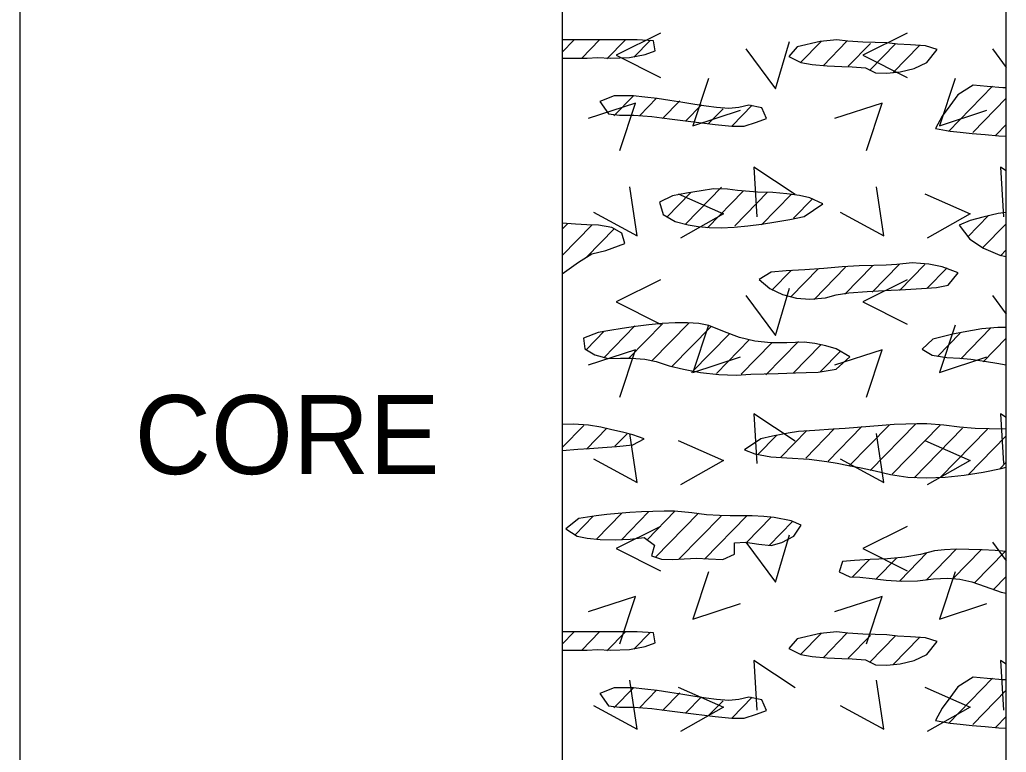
# Model space of a CAD drawing. Extents: x -0.01 to 0.83, y -0.63 to 1.27.
# Drawn here: x 0.75 to 0.8333, y -0.3617 to -0.2998 of the extents above; entities that cross this region are included whole.
import ezdxf

# ---------------------------------------------------------------- set-up
doc = ezdxf.new("R2010")
doc.units = 0

msp = doc.modelspace()

# ---------------------------------------------------------------- linework, layer by layer
for points in [[(0.749999, 1.220831), (0.749999, -0.621832)], [(0.749999, 1.220831), (0.749999, -0.621832)], [(0.795832, 1.220831), (0.795832, -0.621832)], [(0.833332, -0.621832), (0.833332, 1.138431)], [(0.795832, -0.302518), (0.796808, -0.301518)], [(0.798985, -0.3015), (0.797473, -0.303049)], [(0.801161, -0.301483), (0.799593, -0.30309)], [(0.804125, -0.300918), (0.800375, -0.302793), (0.804125, -0.304668)], [(0.803281, -0.301523), (0.801883, -0.302955)], [(0.811342, -0.302259), (0.813842, -0.305634), (0.815029, -0.301634)], [(0.817701, -0.301624), (0.815961, -0.303407)], [(0.819878, -0.301607), (0.817852, -0.303683)], [(0.824958, -0.300918), (0.821208, -0.302793), (0.824958, -0.304668)], [(0.821854, -0.301795), (0.819972, -0.303724)], [(0.824002, -0.301807), (0.821778, -0.304086)], [(0.826007, -0.301964), (0.823783, -0.304244)], [(0.832175, -0.302259), (0.833332, -0.30382)], [(0.808181, -0.30475), (0.806868, -0.30875), (0.810868, -0.307437)], [(0.829014, -0.30475), (0.827702, -0.30875), (0.831702, -0.307437)], [(0.832167, -0.30541), (0.828441, -0.309228)], [(0.801877, -0.306184), (0.800195, -0.307907)], [(0.803798, -0.306428), (0.80237, -0.307891)], [(0.805745, -0.306645), (0.804291, -0.308135)], [(0.833332, -0.306429), (0.830521, -0.309309)], [(0.800689, -0.31083), (0.802002, -0.30683), (0.798002, -0.308142)], [(0.80758, -0.306978), (0.806268, -0.308323)], [(0.809414, -0.307311), (0.808159, -0.308597)], [(0.811876, -0.307001), (0.810165, -0.308755)], [(0.821523, -0.31083), (0.822835, -0.30683), (0.818835, -0.308142)], [(0.833332, -0.308642), (0.832451, -0.309545)], [(0.815512, -0.314556), (0.812012, -0.312243), (0.812262, -0.316431)], [(0.833332, -0.312565), (0.832845, -0.312243), (0.833095, -0.316431)], [(0.798466, -0.316038), (0.802154, -0.318038), (0.801529, -0.313913)], [(0.806256, -0.317028), (0.809278, -0.313931)], [(0.8193, -0.316038), (0.822987, -0.318038), (0.822362, -0.313913)], [(0.804649, -0.316461), (0.806674, -0.314386)], [(0.805617, -0.314493), (0.809456, -0.316177), (0.805806, -0.318238)], [(0.80809, -0.317361), (0.811113, -0.314264)], [(0.810409, -0.317197), (0.813175, -0.314363)], [(0.812643, -0.317121), (0.815181, -0.314521)], [(0.815361, -0.316549), (0.816987, -0.314883)], [(0.82645, -0.314493), (0.83029, -0.316177), (0.826639, -0.318238)], [(0.830098, -0.318123), (0.831838, -0.31634)], [(0.796303, -0.317007), (0.795832, -0.317491)], [(0.798338, -0.317135), (0.795832, -0.319703)], [(0.797862, -0.319835), (0.800229, -0.31741)], [(0.831305, -0.319098), (0.833332, -0.317022)], [(0.832854, -0.319724), (0.833332, -0.319235)], [(0.815145, -0.323201), (0.817482, -0.320806)], [(0.817092, -0.323419), (0.819744, -0.320702)], [(0.819696, -0.322963), (0.822034, -0.320566)], [(0.822015, -0.3228), (0.824297, -0.320462)], [(0.824306, -0.322665), (0.826445, -0.320473)], [(0.826625, -0.322501), (0.828336, -0.320748)], [(0.815192, -0.32094), (0.813538, -0.322635)], [(0.804125, -0.321751), (0.800375, -0.323626), (0.804125, -0.325501)], [(0.811342, -0.323092), (0.813842, -0.326467), (0.815029, -0.322467)], [(0.824958, -0.321751), (0.821208, -0.323626), (0.824958, -0.325501)], [(0.832175, -0.323092), (0.833332, -0.324654)], [(0.799328, -0.328345), (0.801951, -0.325657)], [(0.801419, -0.328416), (0.804299, -0.325464)], [(0.806532, -0.325388), (0.803395, -0.328603)], [(0.805059, -0.329111), (0.808397, -0.325691)], [(0.808181, -0.325583), (0.806868, -0.329583), (0.810868, -0.32827)], [(0.829014, -0.325583), (0.827702, -0.329583), (0.831702, -0.32827)], [(0.832025, -0.325824), (0.829489, -0.328424)], [(0.799375, -0.326083), (0.797863, -0.327633)], [(0.809973, -0.326288), (0.806747, -0.329594)], [(0.827512, -0.328236), (0.82945, -0.326251)], [(0.811636, -0.326796), (0.808841, -0.32966)], [(0.813527, -0.327072), (0.810936, -0.329726)], [(0.813032, -0.329792), (0.815789, -0.326966)], [(0.815342, -0.329637), (0.817681, -0.327241)], [(0.831379, -0.328699), (0.833332, -0.326698)], [(0.800689, -0.331663), (0.802002, -0.327663), (0.798002, -0.328976)], [(0.817605, -0.329532), (0.819344, -0.327749)], [(0.821523, -0.331663), (0.822835, -0.327663), (0.818835, -0.328976)], [(0.833327, -0.328915), (0.833332, -0.32891)], [(0.815512, -0.335389), (0.812012, -0.333077), (0.812262, -0.337264)], [(0.833332, -0.333398), (0.832845, -0.333077), (0.833095, -0.337264)], [(0.797655, -0.334062), (0.795832, -0.335931)], [(0.818285, -0.337083), (0.821137, -0.334161)], [(0.820035, -0.337503), (0.823455, -0.333998)], [(0.825691, -0.333921), (0.82184, -0.337866)], [(0.827752, -0.334021), (0.823702, -0.33817)], [(0.799604, -0.334278), (0.797864, -0.336061)], [(0.798466, -0.336872), (0.802154, -0.338872), (0.801529, -0.334747)], [(0.801295, -0.334757), (0.800268, -0.335809)], [(0.813923, -0.334915), (0.812354, -0.336522)], [(0.814303, -0.336738), (0.816499, -0.334489)], [(0.816395, -0.336808), (0.818789, -0.334353)], [(0.8193, -0.336872), (0.822987, -0.338872), (0.822362, -0.334747)], [(0.829644, -0.334296), (0.825565, -0.338474)], [(0.831735, -0.334365), (0.827743, -0.338455)], [(0.833332, -0.334942), (0.830118, -0.338235)], [(0.805617, -0.335327), (0.809456, -0.33701), (0.805806, -0.339072)], [(0.82645, -0.335327), (0.83029, -0.33701), (0.826639, -0.339072)], [(0.832808, -0.337691), (0.833332, -0.337155)], [(0.79871, -0.343662), (0.800849, -0.341471)], [(0.800827, -0.343706), (0.803111, -0.341366)], [(0.805344, -0.341291), (0.802987, -0.343706)], [(0.80367, -0.345218), (0.807321, -0.341477)], [(0.798444, -0.341722), (0.796912, -0.343292)], [(0.805714, -0.345336), (0.809241, -0.341722)], [(0.811418, -0.341705), (0.807854, -0.345358)], [(0.811407, -0.343929), (0.81348, -0.341804)], [(0.815282, -0.34217), (0.813313, -0.344188)], [(0.804125, -0.342584), (0.800375, -0.344459), (0.804125, -0.346334)], [(0.811342, -0.343925), (0.813842, -0.3473), (0.815029, -0.3433)], [(0.824958, -0.342584), (0.821208, -0.344459), (0.824958, -0.346334)], [(0.832175, -0.343925), (0.833332, -0.345487)], [(0.824327, -0.347193), (0.82666, -0.344803)], [(0.829094, -0.34452), (0.826565, -0.347113)], [(0.828848, -0.346985), (0.831218, -0.344557)], [(0.833245, -0.344692), (0.830651, -0.347351)], [(0.820346, -0.346847), (0.821763, -0.345395)], [(0.822335, -0.347022), (0.824076, -0.345237)], [(0.808181, -0.346416), (0.806868, -0.350416), (0.810868, -0.349104)], [(0.829014, -0.346416), (0.827702, -0.350416), (0.831702, -0.349104)], [(0.833332, -0.346817), (0.832267, -0.347909)], [(0.800689, -0.352497), (0.802002, -0.348497), (0.798002, -0.349809)], [(0.821523, -0.352497), (0.822835, -0.348497), (0.818835, -0.349809)], [(0.795832, -0.352518), (0.796808, -0.351518)], [(0.798985, -0.3515), (0.797473, -0.353049)], [(0.801161, -0.351483), (0.799593, -0.35309)], [(0.803281, -0.351523), (0.801883, -0.352955)], [(0.817701, -0.351624), (0.815961, -0.353407)], [(0.819878, -0.351607), (0.817852, -0.353683)], [(0.821854, -0.351795), (0.819972, -0.353724)], [(0.824002, -0.351806), (0.821778, -0.354086)], [(0.826007, -0.351964), (0.823783, -0.354244)], [(0.815512, -0.356223), (0.812012, -0.35391), (0.812262, -0.358098)], [(0.833332, -0.354232), (0.832845, -0.35391), (0.833095, -0.358098)], [(0.798466, -0.357705), (0.802154, -0.359705), (0.801529, -0.35558)], [(0.8193, -0.357705), (0.822987, -0.359705), (0.822362, -0.35558)], [(0.832167, -0.35541), (0.828441, -0.359227)], [(0.801877, -0.356184), (0.800195, -0.357907)], [(0.803798, -0.356428), (0.80237, -0.35789)], [(0.805745, -0.356645), (0.804291, -0.358135)], [(0.805617, -0.35616), (0.809456, -0.357843), (0.805806, -0.359905)], [(0.82645, -0.35616), (0.83029, -0.357843), (0.826639, -0.359905)], [(0.833332, -0.356429), (0.830521, -0.359309)], [(0.80758, -0.356978), (0.806268, -0.358323)], [(0.809414, -0.357311), (0.808159, -0.358597)], [(0.811876, -0.357001), (0.810165, -0.358755)], [(0.833332, -0.358642), (0.832451, -0.359544)]]:
    msp.add_lwpolyline(points)
for points in [[(0.795832, -0.303037), (0.796757, -0.303047), (0.797925, -0.303028), (0.798816, -0.302989), (0.799915, -0.303032), (0.801515, -0.302988), (0.802823, -0.302732), (0.803666, -0.302412), (0.80354, -0.301573), (0.802165, -0.301488), (0.795832, -0.301488)], [(0.818216, -0.303682), (0.819444, -0.303741), (0.820325, -0.303781), (0.821453, -0.303849), (0.822286, -0.304263), (0.82324, -0.304307), (0.824378, -0.304202), (0.825554, -0.303914), (0.826624, -0.303409), (0.82749, -0.302312), (0.826513, -0.302009), (0.825239, -0.301908), (0.82413, -0.301844), (0.823236, -0.301738), (0.822257, -0.301719), (0.821211, -0.301695), (0.819948, -0.301604), (0.819024, -0.301488), (0.817611, -0.301627), (0.815663, -0.302071), (0.814958, -0.30291), (0.815983, -0.303398), (0.816947, -0.303574)], [(0.833053, -0.305536), (0.831709, -0.305424), (0.830539, -0.305323), (0.829246, -0.306143), (0.828567, -0.307057), (0.827924, -0.307944), (0.827345, -0.308971), (0.828579, -0.309196), (0.829451, -0.309297), (0.830451, -0.309394), (0.831549, -0.309489), (0.832716, -0.309586), (0.833332, -0.309637), (0.833332, -0.305545)], [(0.800664, -0.307839), (0.801881, -0.307846), (0.803392, -0.307974), (0.804229, -0.30807), (0.805103, -0.30818), (0.806004, -0.308298), (0.806919, -0.308419), (0.807838, -0.308537), (0.808747, -0.308647), (0.810142, -0.308789), (0.811186, -0.308777), (0.812223, -0.308432), (0.81308, -0.308147), (0.812673, -0.307245), (0.811597, -0.306998), (0.810749, -0.307196), (0.809892, -0.307279), (0.808847, -0.307198), (0.807995, -0.307087), (0.807033, -0.306943), (0.805997, -0.30678), (0.804922, -0.306612), (0.803843, -0.306455), (0.802797, -0.306323), (0.801817, -0.306231), (0.800202, -0.306222), (0.799007, -0.306695), (0.79974, -0.307738)], [(0.812326, -0.314344), (0.810635, -0.314226), (0.809773, -0.314092), (0.808601, -0.314085), (0.807553, -0.314229), (0.806321, -0.314428), (0.805133, -0.314671), (0.804031, -0.315192), (0.804359, -0.316253), (0.805363, -0.31682), (0.806466, -0.317118), (0.807303, -0.317269), (0.80824, -0.317345), (0.80926, -0.317354), (0.810349, -0.317303), (0.811489, -0.317201), (0.812666, -0.317054), (0.813863, -0.31687), (0.815063, -0.316657), (0.816252, -0.316423), (0.81783, -0.315342), (0.816735, -0.314843), (0.815852, -0.314641), (0.814797, -0.314483), (0.813609, -0.314381)], [(0.832654, -0.316157), (0.831362, -0.316466), (0.830275, -0.316741), (0.829339, -0.317135), (0.830265, -0.318335), (0.831418, -0.319098), (0.832792, -0.319676), (0.833332, -0.319775), (0.833332, -0.316066)], [(0.795832, -0.321253), (0.79719, -0.320263), (0.798312, -0.319561), (0.799509, -0.31929), (0.801112, -0.318689), (0.800861, -0.317805), (0.800021, -0.317329), (0.798893, -0.317135), (0.797908, -0.317105), (0.796943, -0.317048), (0.795832, -0.316966)], [(0.825375, -0.32031), (0.824078, -0.32046), (0.823187, -0.320517), (0.822142, -0.320541), (0.820907, -0.320578), (0.819474, -0.32067), (0.817918, -0.320791), (0.816318, -0.320911), (0.814751, -0.321003), (0.813476, -0.321104), (0.812472, -0.321743), (0.813366, -0.322504), (0.814436, -0.323009), (0.815612, -0.323297), (0.816749, -0.323402), (0.818067, -0.32329), (0.818959, -0.323014), (0.820031, -0.32287), (0.821573, -0.322748), (0.82253, -0.32269), (0.823615, -0.322632), (0.824832, -0.32257), (0.826183, -0.322504), (0.827451, -0.322396), (0.828416, -0.322221), (0.829268, -0.321166), (0.827909, -0.320649), (0.826788, -0.32045)], [(0.798854, -0.326219), (0.797634, -0.32668), (0.797728, -0.327576), (0.798587, -0.328099), (0.799696, -0.328395), (0.800742, -0.328385), (0.801652, -0.328371), (0.802809, -0.328454), (0.803766, -0.328662), (0.804856, -0.329011), (0.80606, -0.329308), (0.807509, -0.329582), (0.809046, -0.329768), (0.810517, -0.329798), (0.811769, -0.329741), (0.812889, -0.3297), (0.814075, -0.329665), (0.815527, -0.329625), (0.816416, -0.329599), (0.817445, -0.329567), (0.818967, -0.329294), (0.820111, -0.328258), (0.818963, -0.327589), (0.818099, -0.327322), (0.817169, -0.327125), (0.816265, -0.32702), (0.814793, -0.327079), (0.813435, -0.327076), (0.812104, -0.326926), (0.810802, -0.326624), (0.809527, -0.326163), (0.808198, -0.325614), (0.807356, -0.325454), (0.806403, -0.32538), (0.805364, -0.325379), (0.804267, -0.325439), (0.803138, -0.325548), (0.802006, -0.325693), (0.800896, -0.325861), (0.799837, -0.326041)], [(0.832629, -0.325773), (0.831261, -0.32591), (0.829688, -0.326175), (0.828826, -0.326349), (0.82712, -0.32676), (0.826226, -0.327628), (0.827084, -0.32812), (0.828308, -0.328307), (0.829408, -0.328372), (0.830335, -0.328461), (0.831655, -0.328644), (0.832526, -0.328786), (0.833332, -0.328928), (0.833332, -0.32578)], [(0.795832, -0.336176), (0.797147, -0.336065), (0.798141, -0.335992), (0.799224, -0.335915), (0.800394, -0.33583), (0.80179, -0.335708), (0.802748, -0.335193), (0.801793, -0.334851), (0.800911, -0.334638), (0.800027, -0.334417), (0.79909, -0.33421), (0.798029, -0.334045), (0.79677, -0.333949), (0.795832, -0.33397)], [(0.828162, -0.338423), (0.82978, -0.338254), (0.831374, -0.338002), (0.832902, -0.337691), (0.833332, -0.337586), (0.833332, -0.334346), (0.832951, -0.334379), (0.831885, -0.334357), (0.830714, -0.334304), (0.829383, -0.334202), (0.828069, -0.334033), (0.826619, -0.333913), (0.825765, -0.333911), (0.824843, -0.333938), (0.823868, -0.333989), (0.822856, -0.334058), (0.82182, -0.334137), (0.820774, -0.334221), (0.819735, -0.334304), (0.818715, -0.334379), (0.817148, -0.334474), (0.815785, -0.334567), (0.814914, -0.3347), (0.813574, -0.334975), (0.812595, -0.335187), (0.811206, -0.336106), (0.812105, -0.336468), (0.813452, -0.336713), (0.814789, -0.336804), (0.816678, -0.336907), (0.818181, -0.337107), (0.819046, -0.337253), (0.820004, -0.337432), (0.821067, -0.337646), (0.82225, -0.337898), (0.823565, -0.33819), (0.825013, -0.338415), (0.826559, -0.338485)], [(0.797084, -0.343405), (0.797938, -0.343583), (0.799042, -0.343695), (0.800285, -0.343729), (0.801555, -0.343675), (0.802742, -0.34352), (0.803614, -0.344182), (0.803377, -0.345079), (0.804221, -0.345349), (0.805167, -0.345368), (0.806129, -0.345312), (0.807202, -0.345281), (0.808182, -0.345312), (0.809387, -0.345386), (0.81037, -0.34492), (0.81038, -0.343973), (0.811296, -0.343911), (0.812442, -0.344098), (0.813463, -0.344204), (0.814379, -0.343948), (0.815394, -0.343406), (0.816006, -0.342493), (0.81517, -0.34212), (0.813738, -0.341844), (0.812849, -0.341751), (0.811872, -0.341693), (0.810001, -0.341691), (0.809104, -0.341673), (0.808002, -0.341599), (0.806784, -0.341442), (0.805305, -0.341312), (0.804427, -0.341298), (0.803488, -0.341314), (0.802511, -0.341355), (0.801521, -0.341417), (0.80054, -0.341495), (0.799593, -0.341586), (0.798702, -0.341685), (0.797221, -0.341908), (0.796138, -0.342786)], [(0.832407, -0.344624), (0.831293, -0.34456), (0.830172, -0.344523), (0.829096, -0.34452), (0.828115, -0.34456), (0.827281, -0.344647), (0.826083, -0.344947), (0.824762, -0.345173), (0.823296, -0.34531), (0.821831, -0.345392), (0.820509, -0.345452), (0.819505, -0.34555), (0.819224, -0.346415), (0.820125, -0.346833), (0.820967, -0.346885), (0.821997, -0.346984), (0.823181, -0.347114), (0.824476, -0.347203), (0.825838, -0.347178), (0.82719, -0.347014), (0.828356, -0.346947), (0.829402, -0.347028), (0.830435, -0.347261), (0.831559, -0.347652), (0.832909, -0.348142), (0.833332, -0.348218), (0.833332, -0.344699)], [(0.795832, -0.353037), (0.796757, -0.353047), (0.797925, -0.353028), (0.798816, -0.352989), (0.799915, -0.353032), (0.801515, -0.352988), (0.802823, -0.352731), (0.803666, -0.352412), (0.80354, -0.351573), (0.802165, -0.351488), (0.795832, -0.351488)], [(0.818216, -0.353682), (0.819444, -0.353741), (0.820325, -0.353781), (0.821453, -0.353849), (0.822286, -0.354263), (0.82324, -0.354307), (0.824378, -0.354202), (0.825554, -0.353913), (0.826624, -0.353409), (0.82749, -0.352312), (0.826513, -0.352009), (0.825239, -0.351908), (0.82413, -0.351844), (0.823236, -0.351738), (0.822257, -0.351719), (0.821211, -0.351695), (0.819948, -0.351603), (0.819024, -0.351488), (0.817611, -0.351627), (0.815663, -0.352071), (0.814958, -0.35291), (0.815983, -0.353398), (0.816947, -0.353574)], [(0.833053, -0.355536), (0.831709, -0.355424), (0.830539, -0.355323), (0.829246, -0.356143), (0.828567, -0.357057), (0.827924, -0.357944), (0.827345, -0.35897), (0.828579, -0.359196), (0.829451, -0.359297), (0.830451, -0.359394), (0.831549, -0.359489), (0.832716, -0.359586), (0.833332, -0.359637), (0.833332, -0.355545)], [(0.800664, -0.357839), (0.801881, -0.357845), (0.803392, -0.357974), (0.804229, -0.35807), (0.805103, -0.35818), (0.806004, -0.358298), (0.806919, -0.358419), (0.807838, -0.358537), (0.808747, -0.358647), (0.810142, -0.358789), (0.811186, -0.358777), (0.812223, -0.358432), (0.81308, -0.358147), (0.812673, -0.357245), (0.811597, -0.356998), (0.810749, -0.357196), (0.809892, -0.357279), (0.808847, -0.357198), (0.807995, -0.357087), (0.807033, -0.356943), (0.805997, -0.356779), (0.804922, -0.356612), (0.803843, -0.356455), (0.802797, -0.356323), (0.801817, -0.356231), (0.800202, -0.356222), (0.799007, -0.356695), (0.79974, -0.357737)]]:
    msp.add_lwpolyline(points, close=True)

# ---------------------------------------------------------------- texts
msp.add_text('CORE', height=0.0066667).set_placement((0.759706, -0.338166))

doc.saveas('drawing.dxf')
